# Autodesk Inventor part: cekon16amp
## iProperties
Created: 2005-11
Part Number: cekon16amp
Document SubType Name: Modeling
Designer: M.Reese
Author: M.Reese
Übersetzungsnorm: STEP AP214DIS
Dateiname: cekon16a.STEP
Vorprozessor: SolidWorks 2005074
Postprozessor: Build: 243, Release: 10 SP1 - Date: Mon 06/06/2005
Gesendete Einheiten: MILLIMETERS
Unbestimmtheit: 1e-05
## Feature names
1. Basis1
